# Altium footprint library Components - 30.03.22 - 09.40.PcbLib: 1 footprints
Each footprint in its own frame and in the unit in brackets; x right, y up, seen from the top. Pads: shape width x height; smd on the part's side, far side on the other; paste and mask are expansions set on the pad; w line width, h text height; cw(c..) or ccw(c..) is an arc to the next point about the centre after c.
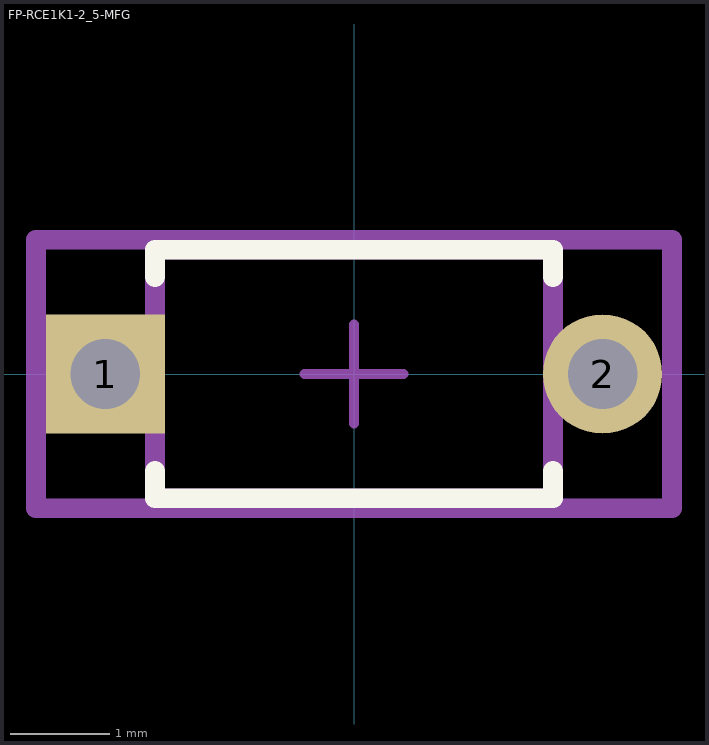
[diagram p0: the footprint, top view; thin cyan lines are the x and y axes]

## FP-RCE1K1-2_5-MFG [mm]
pads (2):
  rect 1.2x1.2 hole 0.7 paste-1000 mask+0: 1(-2.5,0)
  round 1.2 hole 0.7 paste-1000 mask+0: 2(2.5,0)
Top Overlay:
  lines w0.2: -2,-0.975 -2,-1.25 2,-1.25 2,-0.975 ; -2,0.975 -2,1.25 2,1.25 2,0.975
Top Assembly:
  lines w0.2: -3.2,-1.35 -3.2,1.35 3.2,1.35 3.2,-1.35 -3.2,-1.35
  text ".Designator" at 0,0.188 h1
Top 3D Body:
  lines w0.2: -2,-1.25 -2,1.25 2,1.25 2,-1.25 -2,-1.25
Top Courtyard:
  lines w0.2: -3.2,-1.35 -3.2,1.35 3.2,1.35 3.2,-1.35 -3.2,-1.35
Top Component Center:
  lines w0.1: -0.5,0 0.5,0 ; 0,-0.5 0,0.5
3D body "Cap_Murata_RCER71E474K1K1H03B_eec.STEP": height 0.25, standoff 0, extent -3.2,-1.35 3.2,1.35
